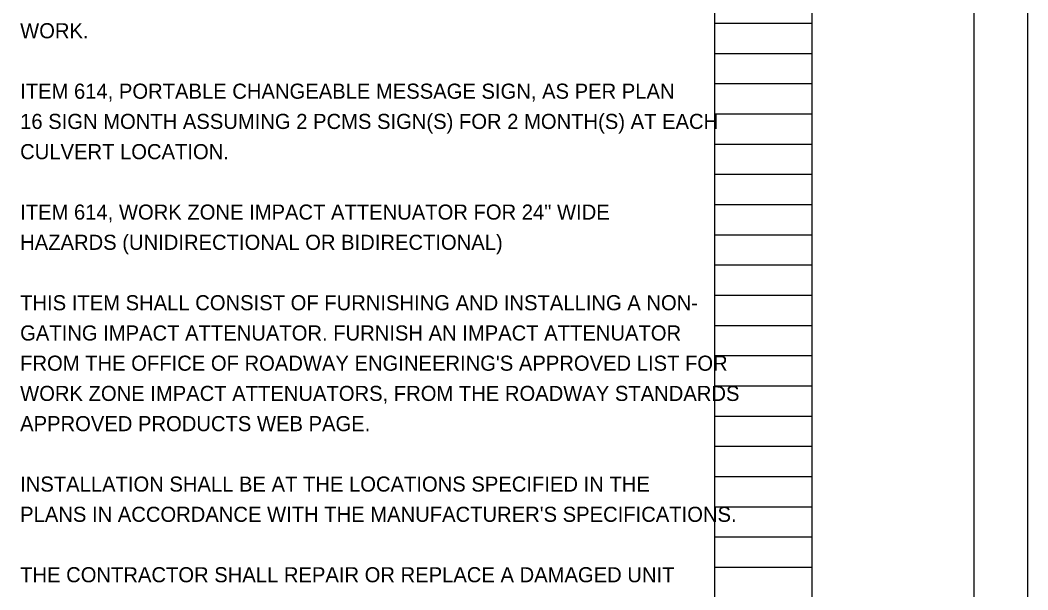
# Model space of a CAD drawing. Extents: x -50 to 112, y -27 to 22.
# Drawn here: x 63.66 to 73, y 4.97 to 10.25 of the extents above; entities that cross this region are included whole.
import ezdxf

# ---------------------------------------------------------------- set-up
doc = ezdxf.new("R2010")
doc.units = 0
for name, color, linetype in [('SC_Scratch1', 7, 'Continuous'), ('SH_Border', 7, 'Continuous'), ('SH_Cut_Line', 7, 'Continuous'), ('SH_Text', 7, 'Continuous')]:
    doc.layers.add(name, color=color, linetype=linetype)

msp = doc.modelspace()

# ---------------------------------------------------------------- linework, layer by layer
at = {"layer": 'SC_Scratch1'}
for p, q in [((70.1, 0.98), (70.1, 21.14)), ((71, 0.98), (71, 21.14)), ((70.1, 10.22), (71, 10.22)), ((70.1, 9.94), (71, 9.94)), ((70.1, 9.66), (71, 9.66)), ((70.1, 9.38), (71, 9.38)), ((70.1, 9.1), (71, 9.1)), ((70.1, 8.82), (71, 8.82)), ((70.1, 8.54), (71, 8.54)), ((70.1, 8.26), (71, 8.26)), ((70.1, 7.98), (71, 7.98)), ((70.1, 7.7), (71, 7.7)), ((70.1, 7.42), (71, 7.42)), ((70.1, 7.14), (71, 7.14)), ((70.1, 6.86), (71, 6.86)), ((70.1, 6.58), (71, 6.58)), ((70.1, 6.3), (71, 6.3)), ((70.1, 6.02), (71, 6.02)), ((70.1, 5.74), (71, 5.74)), ((70.1, 5.46), (71, 5.46)), ((70.1, 5.18), (71, 5.18))]:
    msp.add_line(p, q, dxfattribs=at)
at = {"layer": 'SH_Border'}
msp.add_line((71, 0.5), (71, 21.5), dxfattribs=at)
msp.add_lwpolyline([(40.5, 21.5), (72.5, 21.5), (72.5, 0.5), (40.5, 0.5)], close=True, dxfattribs=at)
at = {"layer": 'SH_Cut_Line'}
msp.add_lwpolyline([(39, 0), (73, 0), (73, 22), (39, 22)], close=True, dxfattribs=at)

# ---------------------------------------------------------------- texts
at = {"layer": 'SH_Text'}
for s, p in [('WORK.', (63.66, 10.08)), ('ITEM 614, PORTABLE CHANGEABLE MESSAGE SIGN, AS PER PLAN ', (63.66, 9.52)), ('16 SIGN MONTH ASSUMING 2 PCMS SIGN(S) FOR 2 MONTH(S) AT EACH ', (63.66, 9.24)), ('CULVERT LOCATION.', (63.66, 8.96)), ('ITEM 614, WORK ZONE IMPACT ATTENUATOR FOR 24" WIDE', (63.66, 8.4)), ('HAZARDS (UNIDIRECTIONAL OR BIDIRECTIONAL)', (63.66, 8.12)), ('THIS ITEM SHALL CONSIST OF FURNISHING AND INSTALLING A NON-', (63.66, 7.56)), ('GATING IMPACT ATTENUATOR. FURNISH AN IMPACT ATTENUATOR ', (63.66, 7.28)), ("FROM THE OFFICE OF ROADWAY ENGINEERING'S APPROVED LIST FOR ", (63.66, 7)), ('WORK ZONE IMPACT ATTENUATORS, FROM THE ROADWAY STANDARDS ', (63.66, 6.72)), ('APPROVED PRODUCTS WEB PAGE. ', (63.66, 6.44)), ('INSTALLATION SHALL BE AT THE LOCATIONS SPECIFIED IN THE ', (63.66, 5.88)), ("PLANS IN ACCORDANCE WITH THE MANUFACTURER'S SPECIFICATIONS. ", (63.66, 5.6)), ('THE CONTRACTOR SHALL REPAIR OR REPLACE A DAMAGED UNIT ', (63.66, 5.04))]:
    msp.add_text(s, height=0.14, dxfattribs=at).set_placement(p)

doc.saveas('drawing.dxf')
